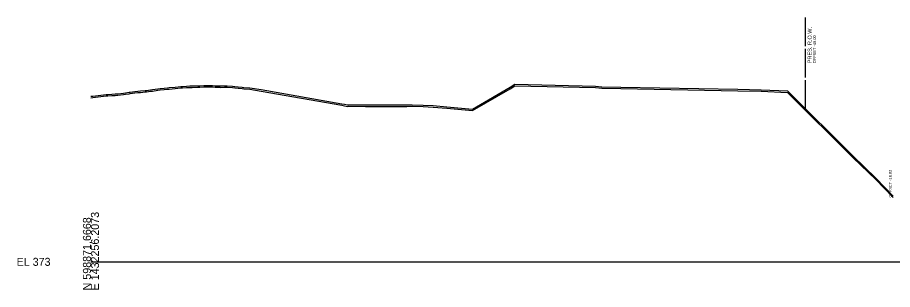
# Model space of a CAD drawing. Extents: x -26 to 2203, y -10 to 12201.
# Drawn here: x -25.7 to 280.4, y 10490.3 to 10585.6 of the extents above; entities that cross this region are included whole.
import ezdxf

# ---------------------------------------------------------------- set-up
doc = ezdxf.new("R2010")
doc.units = 0
for name, color, linetype in [('DESIGN - SHEET - Light Grid', 7, 'Continuous'), ('DESIGN - TYPICAL - Slope Tie Text', 7, 'Continuous'), ('SURVEY - GROUND - Bottom of Topsoil Layer', 7, 'Continuous'), ('SURVEY - GROUND - Top of Ground', 7, 'Continuous'), ('SURVEY - PROPERTY - ROW Lines', 7, 'Continuous'), ('SURVEY - PROPERTY - ROW Lines Text', 7, 'Continuous')]:
    doc.layers.add(name, color=color, linetype=linetype)

msp = doc.modelspace()

# ---------------------------------------------------------------- linework, layer by layer
at = {"layer": 'DESIGN - SHEET - Light Grid'}
msp.add_line((0, 10500), (300, 10500), dxfattribs=at)
at = {"layer": 'SURVEY - GROUND - Bottom of Topsoil Layer'}
for p, q in [((33.43, 10561.01), (34.64, 10561.07)), ((34.64, 10561.07), (35.44, 10561.09)), ((35.44, 10561.09), (37.45, 10561.13)), ((37.45, 10561.13), (38.1, 10561.17)), ((38.1, 10561.17), (39.45, 10561.23)), ((39.45, 10561.23), (39.86, 10561.24)), ((39.86, 10561.24), (41.46, 10561.22)), ((41.46, 10561.22), (42.47, 10561.22)), ((42.47, 10561.22), (43.47, 10561.17)), ((43.47, 10561.17), (45.08, 10561.1)), ((45.08, 10561.1), (45.47, 10561.08)), ((45.47, 10561.08), (46.76, 10561.11)), ((46.76, 10561.11), (47.7, 10561.1)), ((47.7, 10561.1), (49.49, 10560.99)), ((146.64, 10560.6), (148.33, 10561.66)), ((148.33, 10561.66), (176.55, 10560.99)), ((3.46, 10557.87), (5.35, 10558.07)), ((5.35, 10558.07), (5.91, 10558.13)), ((5.91, 10558.13), (7.35, 10558.2)), ((7.35, 10558.2), (8.53, 10558.27)), ((8.53, 10558.27), (9.36, 10558.35)), ((9.36, 10558.35), (11.37, 10558.6)), ((11.37, 10558.6), (12.12, 10558.71)), ((12.12, 10558.71), (13.37, 10558.88)), ((13.37, 10558.88), (13.75, 10558.94)), ((13.75, 10558.94), (15.38, 10559.12)), ((15.38, 10559.12), (16.36, 10559.24)), ((16.36, 10559.24), (17.38, 10559.34)), ((17.38, 10559.34), (18.97, 10559.47)), ((18.97, 10559.47), (19.39, 10559.53)), ((19.39, 10559.53), (20.78, 10559.71)), ((20.78, 10559.71), (21.58, 10559.81)), ((21.58, 10559.81), (23.4, 10560.08)), ((23.4, 10560.08), (24.19, 10560.19)), ((24.19, 10560.19), (25.67, 10560.33)), ((25.67, 10560.33), (26.81, 10560.44)), ((26.81, 10560.44), (27.42, 10560.49)), ((27.42, 10560.49), (29.44, 10560.66)), ((29.44, 10560.66), (31.43, 10560.89)), ((31.43, 10560.89), (32.03, 10560.94)), ((32.03, 10560.94), (33.43, 10561.01)), ((49.49, 10560.99), (50.31, 10560.93)), ((50.31, 10560.93), (51.49, 10560.76)), ((51.49, 10560.76), (52.92, 10560.67)), ((52.92, 10560.67), (53.5, 10560.58)), ((53.5, 10560.58), (55.55, 10560.43)), ((55.55, 10560.43), (59.53, 10559.79)), ((59.53, 10559.79), (87.72, 10554.83)), ((133.47, 10552.97), (146.64, 10560.6)), ((176.55, 10560.99), (178.78, 10560.81)), ((178.78, 10560.81), (185.38, 10560.71)), ((185.38, 10560.71), (226.36, 10559.91)), ((226.36, 10559.91), (234.51, 10559.74)), ((234.51, 10559.74), (243.68, 10559.34)), ((243.68, 10559.34), (266.7, 10536.46)), ((0, 10557.45), (0.69, 10557.51)), ((0.69, 10557.51), (3.46, 10557.87)), ((87.72, 10554.83), (88.73, 10554.67)), ((88.73, 10554.67), (89.75, 10554.44)), ((89.75, 10554.44), (90.22, 10554.46)), ((90.22, 10554.46), (96.03, 10554.44)), ((96.03, 10554.44), (106.63, 10554.43)), ((106.63, 10554.43), (110.5, 10554.42)), ((110.5, 10554.42), (112.36, 10554.52)), ((112.36, 10554.52), (116.21, 10554.38)), ((116.21, 10554.38), (119.77, 10554.2)), ((119.77, 10554.2), (124.49, 10553.82)), ((124.49, 10553.82), (133.47, 10552.97)), ((266.7, 10536.46), (274.62, 10528.77)), ((274.62, 10528.77), (280.65, 10522.49))]:
    msp.add_line(p, q, dxfattribs=at)
at = {"layer": 'SURVEY - GROUND - Top of Ground'}
for p, q in [((27.42, 10560.99), (29.44, 10561.16)), ((29.44, 10561.16), (31.43, 10561.39)), ((31.43, 10561.39), (32.03, 10561.44)), ((32.03, 10561.44), (33.43, 10561.51)), ((33.43, 10561.51), (34.64, 10561.57)), ((34.64, 10561.57), (35.44, 10561.59)), ((35.44, 10561.59), (37.45, 10561.63)), ((37.45, 10561.63), (38.1, 10561.67)), ((38.1, 10561.67), (39.45, 10561.73)), ((39.45, 10561.73), (39.86, 10561.74)), ((39.86, 10561.74), (41.46, 10561.72)), ((41.46, 10561.72), (42.47, 10561.72)), ((42.47, 10561.72), (43.47, 10561.67)), ((43.47, 10561.67), (45.08, 10561.6)), ((45.08, 10561.6), (45.47, 10561.58)), ((45.47, 10561.58), (46.76, 10561.61)), ((46.76, 10561.61), (47.7, 10561.6)), ((47.7, 10561.6), (49.49, 10561.49)), ((49.49, 10561.49), (50.31, 10561.43)), ((50.31, 10561.43), (51.49, 10561.26)), ((51.49, 10561.26), (52.92, 10561.17)), ((52.92, 10561.17), (53.5, 10561.08)), ((53.5, 10561.08), (55.55, 10560.93)), ((133.47, 10553.47), (146.64, 10561.1)), ((146.64, 10561.1), (148.33, 10562.16)), ((148.33, 10562.16), (176.55, 10561.49)), ((176.55, 10561.49), (178.78, 10561.31)), ((178.78, 10561.31), (185.38, 10561.21)), ((185.38, 10561.21), (226.36, 10560.41)), ((0, 10557.95), (0.69, 10558.01)), ((0.69, 10558.01), (3.46, 10558.37)), ((3.46, 10558.37), (5.35, 10558.57)), ((5.35, 10558.57), (5.91, 10558.63)), ((5.91, 10558.63), (7.35, 10558.7)), ((7.35, 10558.7), (8.53, 10558.77)), ((8.53, 10558.77), (9.36, 10558.85)), ((9.36, 10558.85), (11.37, 10559.1)), ((11.37, 10559.1), (12.12, 10559.21)), ((12.12, 10559.21), (13.37, 10559.38)), ((13.37, 10559.38), (13.75, 10559.44)), ((13.75, 10559.44), (15.38, 10559.62)), ((15.38, 10559.62), (16.36, 10559.74)), ((16.36, 10559.74), (17.38, 10559.84)), ((17.38, 10559.84), (18.97, 10559.97)), ((18.97, 10559.97), (19.39, 10560.03)), ((19.39, 10560.03), (20.78, 10560.21)), ((20.78, 10560.21), (21.58, 10560.31)), ((21.58, 10560.31), (23.4, 10560.58)), ((23.4, 10560.58), (24.19, 10560.69)), ((24.19, 10560.69), (25.67, 10560.83)), ((25.67, 10560.83), (26.81, 10560.94)), ((26.81, 10560.94), (27.42, 10560.99)), ((55.55, 10560.93), (59.53, 10560.29)), ((59.53, 10560.29), (87.72, 10555.33)), ((226.36, 10560.41), (234.51, 10560.24)), ((234.51, 10560.24), (243.68, 10559.84)), ((243.68, 10559.84), (266.7, 10536.96)), ((87.72, 10555.33), (88.73, 10555.17)), ((88.73, 10555.17), (89.75, 10554.94)), ((89.75, 10554.94), (90.22, 10554.96)), ((90.22, 10554.96), (96.03, 10554.94)), ((96.03, 10554.94), (106.63, 10554.93)), ((106.63, 10554.93), (110.5, 10554.92)), ((110.5, 10554.92), (112.36, 10555.02)), ((112.36, 10555.02), (116.21, 10554.88)), ((116.21, 10554.88), (119.77, 10554.7)), ((119.77, 10554.7), (124.49, 10554.32)), ((124.49, 10554.32), (133.47, 10553.47)), ((266.7, 10536.96), (274.62, 10529.27)), ((274.62, 10529.27), (280.65, 10522.99))]:
    msp.add_line(p, q, dxfattribs=at)
at = {"layer": 'SURVEY - PROPERTY - ROW Lines'}
for p, q in [((250, 10575.56), (250, 10585.56)), ((250, 10564.56), (250, 10574.56)), ((250, 10553.56), (250, 10563.56))]:
    msp.add_line(p, q, dxfattribs=at)

# ---------------------------------------------------------------- texts
at = {"layer": 'DESIGN - SHEET - Light Grid'}
for s, p in [('N 598871.6668', (0, 10490)), ('E 1432256.2073', (2.8, 10490))]:
    msp.add_text(s, height=2.8, rotation=90, dxfattribs=at).set_placement(p)
msp.add_text('EL 373', height=2.8, dxfattribs=at).set_placement((-26, 10498.6))
at = {"layer": 'DESIGN - TYPICAL - Slope Tie Text'}
msp.add_text('OFFSET -18.82', height=1, rotation=90, dxfattribs=at).set_placement((280.18, 10522.52))
at = {"layer": 'SURVEY - PROPERTY - ROW Lines Text'}
for s, height, p in [('PRES. R.O.W.', 1.4, (252.15, 10569.56)), ('OFFSET -49.00', 1, (253.65, 10569.56))]:
    msp.add_text(s, height=height, rotation=90, dxfattribs=at).set_placement(p)

doc.saveas('drawing.dxf')
